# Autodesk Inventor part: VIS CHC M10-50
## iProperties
Created: 2004-11
Part Number: VIS CHC M10-50
Document SubType Name: Modeling
Designer: Bruno
Manufacturer: Standard
Standards Organization: Custom
Author: Bruno
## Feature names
1. Base1
